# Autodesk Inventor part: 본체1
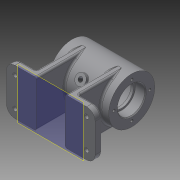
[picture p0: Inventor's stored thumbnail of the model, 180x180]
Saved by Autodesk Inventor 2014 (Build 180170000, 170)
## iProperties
Created: 2017-02
Part Number: 본체1
Material: 일반
Document SubType Name: Modeling
Designer: owner
Density: 1 g/cm^3
Appearance: 기본값
Author: owner
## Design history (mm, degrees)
sketch "스케치1"
  geometry: L1 (0, 0)-(70, 0); L2 (0, 16)-(0, 27); L3 (0, 27)-(70, 27); L4 (70, 27)-(70, 16); L5 (0, 16)-(12, 16); L6 (12, 16)-(12, 14); L7 (12, 14)-(15, 14); L8 (15, 14)-(15, 22); L9 (15, 22)-(55, 22); L10 (55, 22)-(55, 14); L11 (55, 14)-(58, 14); L12 (58, 14)-(58, 16); L13 (58, 16)-(70, 16)
  constraints: 26 end point, 6 parallel, 6 perpendicular, 2 collinear, 2 horizontal alignment, 2 vertical alignment, 1 horizontal
  dimensions: "d0" = 70 distance of L1.start L1.end; "d1" = 54 diameter of L3 L1; "d2" = 32 diameter of L5 L1; "d3" = 28 diameter of L7 L1; "d4" = 44 diameter of L9 L1; "d5" = 12 distance of L4.end L12.end; "d6" = 40 distance of L8.end L9.end
revolve "회전1" sketch "스케치1" stored, may be unused: angle "d7" = 90 deg
node "작업 평면1"
sketch "스케치2"
  geometry: L1 (17, -27)-(17, 27); L2 (-87, 27)-(-87, -27); L3 (-70, 0)-(8.164, 0); L4 (0, 27)-(0, -27) reference; L5 (-52, 27)-(-52, -27); L6 (-18, 27)-(-18, -27); L7 (17, 27)-(-18, 27); L8 (-52, 27)-(-87, 27); L9 (-87, -27)-(-52, -27); L10 (-18, -27)-(17, -27); L11 (-35, 27)-(-35, -27)
  constraints: 20 end point, 8 perpendicular, 4 parallel
  dimensions: "d19" = 52 distance between parallel lines of L2 L11; "d20" = 52 distance between parallel lines of L1 L11; "d21" = 17 distance between parallel lines of L5 L11; "d22" = 17 distance between parallel lines of L6 L11; "d23" = 54 distance of L2.start L2.end
extrude "돌출1" join sketch "스케치2" distance "d24" = 8; taper "d25" = 0 deg
sketch "스케치4"
  geometry: L1 (-17, -27)-(18, -27) reference; L2 (18, -27)-(18, 27) reference; L3 (18, 27)-(-17, 27) reference; L4 (52, 27)-(87, 27) reference; L5 (52, -27)-(52, 27) reference; L6 (87, -27)-(52, -27) reference; L7 (10, -27)-(10, 27); L8 (60, -27)-(60, 27); 1 further point
  constraints: 4 end point, 4 point on line, 2 perpendicular
  dimensions: "d28" = 8 distance between parallel lines of L2 L7; "d29" = 8 distance between parallel lines of L8 L5
extrude "돌출2" join sketch "스케치4" stored distance "d30" = 8; taper "d31" = 0 deg
node "작업 평면2"
sketch "스케치5"
  geometry: L1 (0, 27)-(-70, 27) reference; L2 (-70, 27)-(-70, -27) reference; C1 r 5 at (-45, 0); 1 further point
  constraints: 1 centre point, 1 horizontal alignment
  dimensions: "d33" = 10 diameter of C1; "d52" = 25 distance from line of C1.centre L2
extrude "돌출3" join sketch "스케치5" stored distance "d34" = 8; taper "d35" = 0 deg
hole "구멍1" diameter "d38" = 5.188; stored, may be unused: countersink angle "d42" = 90 deg, drill point angle "d44" = 118 deg; dims "d39" = 6, "d40" = 4, "d41" = 2, "d43" = 10, "d132" = 10, "d133" = 10
node "작업 평면6"
  node "작업 평면5"
sketch "스케치7"
  geometry: L1 (0, 27)-(70, 27) reference; L2 (0, -27)-(0, 27) reference; C1 r 6 at (35, 0); 1 further point
  constraints: 1 centre point, 1 horizontal alignment
  dimensions: "d53" = 12 diameter of C1; "d98" = 35 distance from line of C1.centre L2
extrude "돌출5" join sketch "스케치7" stored distance "d54" = 8; taper "d55" = 0 deg
hole "구멍2" diameter "d58" = 5.188; stored, may be unused: countersink angle "d62" = 90 deg, drill point angle "d64" = 118 deg; dims "d59" = 6, "d60" = 4, "d61" = 2, "d63" = 8, "d65" = 10, "d66" = 10
fillet "모깎기1" dims "d67" = 10
sketch "스케치8" dims "d68" = 9
  geometry: L1 (74.402, 12.5)-(71.804, 17); L2 (71.804, 17)-(74.402, 21.5); L3 (74.402, 21.5)-(79.598, 21.5); L4 (79.598, 21.5)-(82.196, 17); L5 (82.196, 17)-(79.598, 12.5); L6 (79.598, 12.5)-(74.402, 12.5); C1 r 2.5 at (77, 17); A1 r 10 centre (77, 17) between (87, 17) and (77, 27) reference; 7 further points
  constraints: 12 end point, 6 coincident, 1 centre point, 1 midpoint, 1 vertical alignment, 15 other
  dimensions: "d69" = 5 diameter of C1; "d148" = 4.5 vertical distance of L4.end L5.end
sketch "스케치9" dims "d74" = 9, "d75" = 9, "d76" = 9
  geometry: L1 (-4.113, 21.32)-(-1.815, 16.66); L2 (-1.815, 16.66)-(-4.702, 12.34); L3 (-4.702, 12.34)-(-9.887, 12.68); L4 (-9.887, 12.68)-(-12.185, 17.34); L5 (-12.185, 17.34)-(-9.298, 21.66); L6 (-9.298, 21.66)-(-4.113, 21.32); L7 (-4.113, -12.68)-(-1.815, -17.34); L8 (-1.815, -17.34)-(-4.702, -21.66); L9 (-4.702, -21.66)-(-9.887, -21.32); L10 (-9.887, -21.32)-(-12.185, -16.66); L11 (-12.185, -16.66)-(-9.298, -12.34); L12 (-9.298, -12.34)-(-4.113, -12.68); L13 (79.887, -12.68)-(82.185, -17.34); L14 (82.185, -17.34)-(79.298, -21.66); L15 (79.298, -21.66)-(74.113, -21.32); L16 (74.113, -21.32)-(71.815, -16.66); L17 (71.815, -16.66)-(74.702, -12.34); L18 (74.702, -12.34)-(79.887, -12.68); C1 r 2.5 at (-7, 17); C2 r 2.5 at (-7, -17); C3 r 2.5 at (77, -17); A1 r 10 centre (-7, -17) between (-17, -17) and (-7, -27) reference; A2 r 10 centre (-7, 17) between (-7, 27) and (-17, 17) reference; A3 r 10 centre (77, -17) between (77, -27) and (87, -17) reference; 16 further points
  constraints: 36 end point, 15 coincident, 3 centre point, 3 midpoint, 48 other
  dimensions: "d77" = 5 diameter of C1; "d78" = 5 diameter of C2; "d79" = 5 diameter of C3; "d134" = 2.88675 horizontal distance of L17.end L16.end; "d135" = 2.88675 horizontal distance of L10.end L11.end; "d136" = 2.88675 horizontal distance of L4.end L5.end
fillet "모깎기2" dims "d88" = 3
fillet "모깎기3" dims "d89" = 3
chamfer "모따기1" distance "d90" = 1; stored, may be unused: second distance "d91" = 2, angle "d92" = 45 deg
fillet "모깎기4" dims "d93" = 0.3
fillet "모깎기5" dims "d94" = 0.3
sketch "스케치10"
  geometry: C1 r 27 at (0, 0) reference; 1 further point
  constraints: 1 vertical alignment
  dimensions: "d99" = 21 distance of C1.centre point (0, 21)
hole "구멍3" sketch "스케치10" at (0, 21) diameter "d100" = 3.242; stored, may be unused: countersink angle "d104" = 90 deg, drill point angle "d106" = 118 deg; dims "d101" = 8, "d102" = 4, "d103" = 2, "d105" = 10
sketch "스케치11"
  geometry: C1 r 27 at (0, 0) reference; 1 further point
  constraints: 1 vertical alignment
  dimensions: "d110" = 21 distance of C1.centre point (0, 21)
hole "구멍4" sketch "스케치11" at (0, 21) diameter "d111" = 3.242; stored, may be unused: countersink angle "d115" = 90 deg, drill point angle "d117" = 118 deg; dims "d112" = 8, "d113" = 4, "d114" = 2, "d116" = 10
fillet "모깎기15" dims "d130" = 2
fillet "모깎기16" dims "d131" = 2
extrude "돌출12" cut sketch "스케치9" distance "d137" = 4; taper "d138" = 0 deg
extrude "돌출16" cut sketch "스케치8" distance "d146" = 3; taper "d147" = 0 deg
extrude "돌출17" cut sketch "스케치9" stored distance "d149" = 3; taper "d150" = 0 deg
extrude "돌출18" cut sketch "스케치8" distance "d151" = 3; taper "d152" = 0 deg
extrude "돌출19" cut sketch "스케치8" stored distance "d153" = 3; taper "d154" = 0 deg
extrude "돌출20" cut sketch "스케치9" distance "d155" = 3; taper "d156" = 0 deg
extrude "돌출21" cut sketch "스케치9" distance "d157" = 3; taper "d158" = 0 deg
extrude "돌출22" cut sketch "스케치9" distance "d159" = 3; taper "d160" = 0 deg
node "솔리드1"
pattern_circular "원형 패턴1" dims angle "d108" = 360 deg
pattern_circular "원형 패턴2" dims angle "d119" = 360 deg
node "작업축1"
other parameters: "d32" = 92, "d47" = 57 deg
